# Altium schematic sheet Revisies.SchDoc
size A4; CompanyName: Ultimaker; Revision: rev. 2.0.2
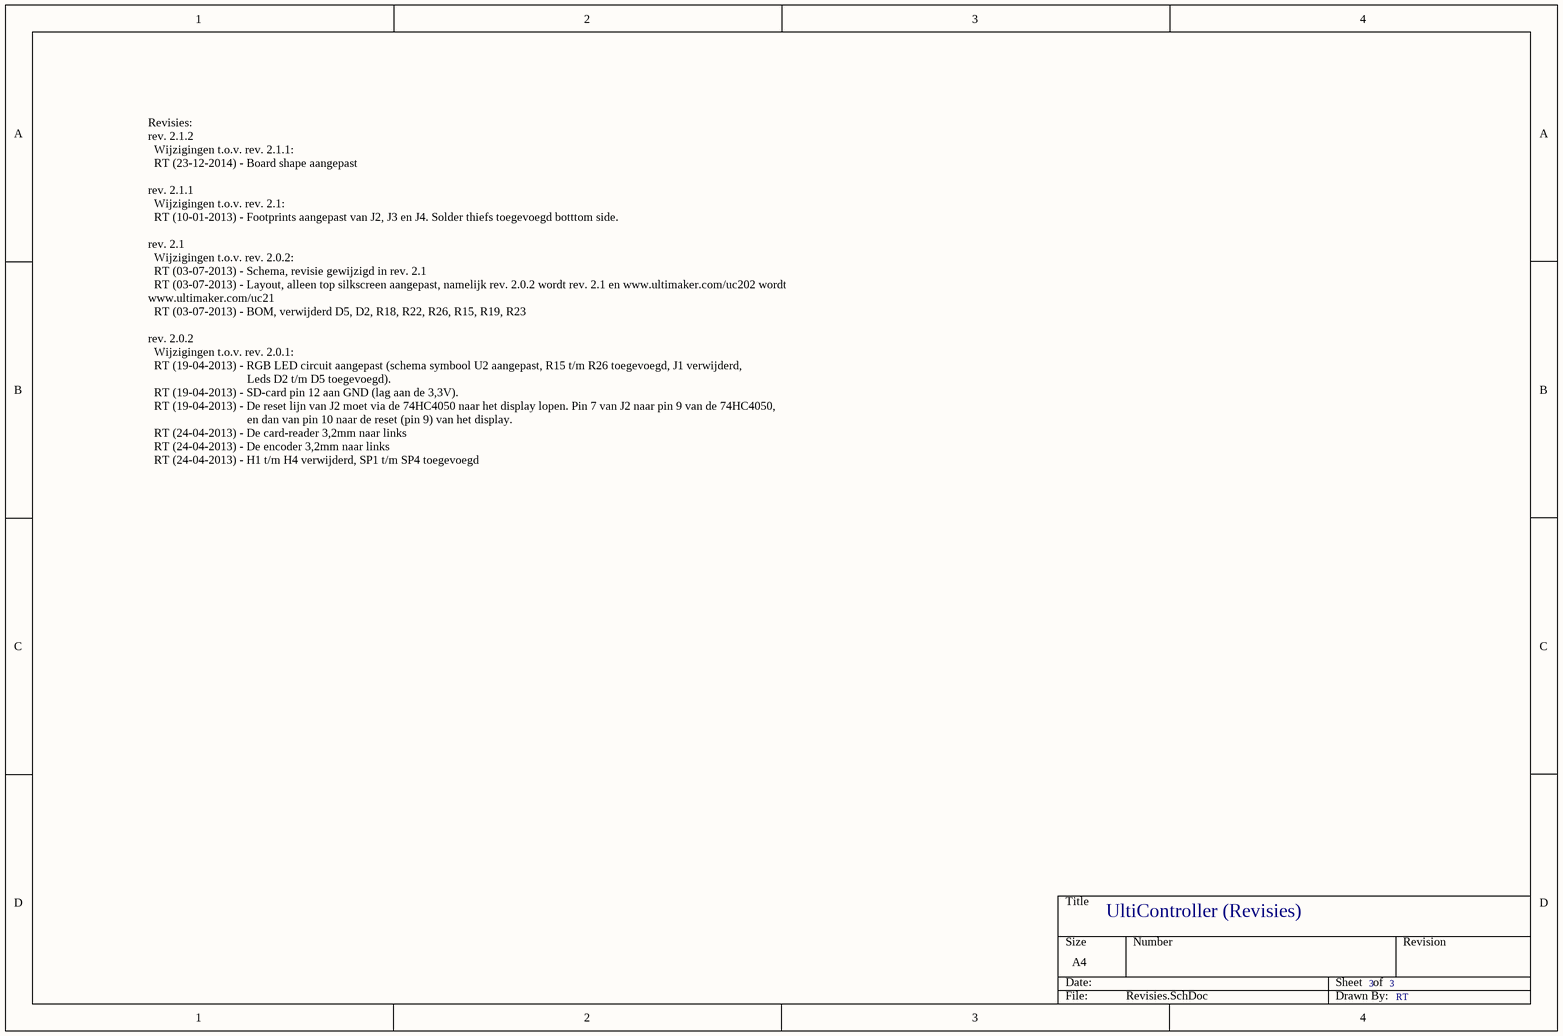
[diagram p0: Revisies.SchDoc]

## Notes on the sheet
- Revisies:
  rev. 2.1.2
  Wijzigingen t.o.v. rev. 2.1.1:
  RT (23-12-2014) - Board shape aangepast
  rev. 2.1.1
  Wijzigingen t.o.v. rev. 2.1:
  RT (10-01-2013) - Footprints aangepast van J2, J3 en J4. Solder thiefs toegevoegd botttom side.
  rev. 2.1
  Wijzigingen t.o.v. rev. 2.0.2:
  RT (03-07-2013) - Schema, revisie gewijzigd in rev. 2.1
  RT (03-07-2013) - Layout, alleen top silkscreen aangepast, namelijk rev. 2.0.2 wordt rev. 2.1 en www.ultimaker.com/uc202 wordt                                      www.ultimaker.com/uc21
  RT (03-07-2013) - BOM, verwijderd D5, D2, R18, R22, R26, R15, R19, R23
  rev. 2.0.2
  Wijzigingen t.o.v. rev. 2.0.1:
  RT (19-04-2013) - RGB LED circuit aangepast (schema symbool U2 aangepast, R15 t/m R26 toegevoegd, J1 verwijderd,
  Leds D2 t/m D5 toegevoegd).
  RT (19-04-2013) - SD-card pin 12 aan GND (lag aan de 3,3V).
  RT (19-04-2013) - De reset lijn van J2 moet via de 74HC4050 naar het display lopen. Pin 7 van J2 naar pin 9 van de 74HC4050,
  en dan van pin 10 naar de reset (pin 9) van het display.
  RT (24-04-2013) - De card-reader 3,2mm naar links
  RT (24-04-2013) - De encoder 3,2mm naar links
  RT (24-04-2013) - H1 t/m H4 verwijderd, SP1 t/m SP4 toegevoegd
- UltiController (Revisies)
- 3
- RT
